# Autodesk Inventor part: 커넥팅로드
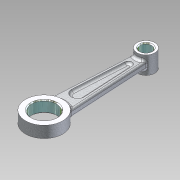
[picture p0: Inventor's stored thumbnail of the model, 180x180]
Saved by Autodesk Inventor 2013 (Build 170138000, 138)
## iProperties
Manager: KYOUNG IL JANG
Company: 한국ATC센터
Created: 2012-10
Part Number: 커넥팅로드
Document SubType Name: Modeling
Density: 1 g/cm^3
Checked By: KYOUNG IL JANG
Vendor: CBT Solutions
Designer: KYOUNG IL JANG
Material: 일반
Author: KYOUNG IL JANG
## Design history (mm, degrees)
sketch "스케치1"
  geometry: L1 (-19.879, 82.758)-(-19.879, 197.758); L2 (-27.379, 191.144)-(-32.379, 99.633); L3 (-12.379, 191.144)-(-7.379, 99.633); C1 r 14 at (-19.879, 82.758); C2 r 6.5 at (-19.879, 197.758); A1 r 19 centre (-19.879, 82.758) between (-20.11, 101.757) and (-19.649, 63.76) reference; A2 r 21 centre (-19.879, 82.758) between (-32.379, 99.633) and (-7.379, 99.633); A3 r 10 centre (-19.879, 197.758) between (-27.379, 191.144) and (-12.379, 191.144); 1 further point
  constraints: 6 end point, 4 centre point, 4 coincident, 4 point on circle, 2 horizontal alignment, 1 equal length, 1 vertical
  dimensions: "d0" = 28 diameter of C1; "d1" = 42 diameter of A2; "d4" = 115 distance of L1.end C1.centre; "d5" = 20 diameter of A3; "d6" = 13 diameter of C2; "d7" = 25 distance of L3.end L2.end; "d8" = 15 distance of L3.start L2.start
  node "참조1"
extrude "돌출1" new body sketch "스케치1" stored distance "d2" = 13; taper "d3" = 0 deg
extrude "돌출2" join sketch "스케치1" stored distance "d9" = 20; taper "d10" = 0 deg
extrude "돌출3" join sketch "스케치1" stored distance "d11" = 8; taper "d12" = 0 deg
sketch "스케치2"
  geometry: L1 (7.379, 99.633)-(12.379, 191.144) reference; L2 (27.379, 191.144)-(32.379, 99.633) reference; L3 (27.197, 121.158)-(24.092, 177.989); L4 (15.667, 177.989)-(12.561, 121.158); A1 r 21 centre (19.879, 82.758) between (7.379, 99.633) and (32.379, 99.633) reference; A2 r 7.329 centre (19.879, 120.758) between (12.561, 121.158) and (27.197, 121.158); A3 r 4.219 centre (19.879, 177.758) between (24.092, 177.989) and (15.667, 177.989); A4 r 10 centre (19.879, 197.758) between (12.379, 191.144) and (27.379, 191.144) reference; 2 further points
  constraints: 4 end point, 4 point on circle, 4 tangent, 2 centre point, 2 parallel, 1 coincident, 3 other
  dimensions: "d16" = 38 distance of A2.centre A1.centre; "d17" = 4 distance between parallel lines of L2 L3; "d18" = 4 distance between parallel lines of L4 L1; "d25" = 20 distance of A3.centre A4.centre
extrude "돌출4" cut sketch "스케치2" distance "d19" = 5; taper "d20" = 0 deg
fillet "모깎기1" dims "d21" = 2
fillet "모깎기2" dims "d22" = 3
fillet "모깎기3" dims "d23" = 3
chamfer "모따기1" distance "d26" = 1; stored, may be unused: second distance "d27" = 2, angle "d28" = 45 deg
chamfer "모따기2" distance "d29" = 1; stored, may be unused: second distance "d30" = 2, angle "d31" = 45 deg
node "솔리드1"
mirror "대칭1"
other parameters: "d13" = 5, "d14" = 5
